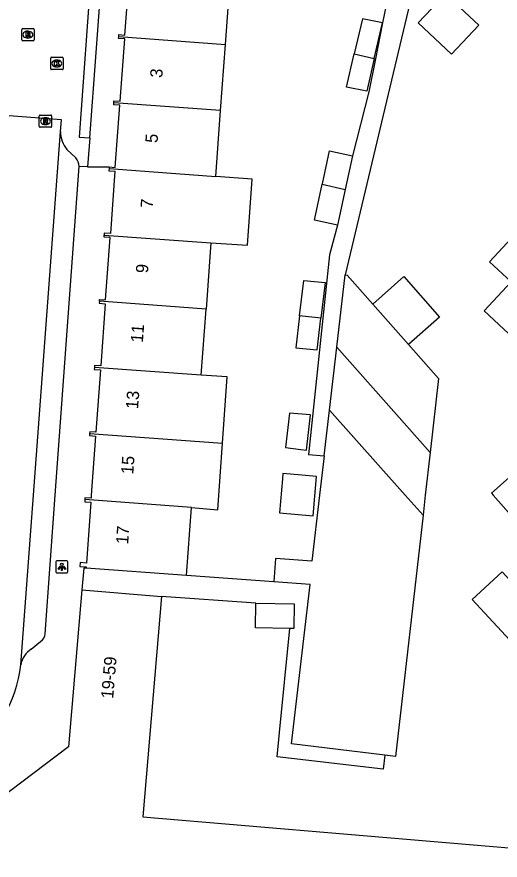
# Model space of a CAD drawing. Extents: x 159961 to 160856, y 382704 to 383353.
# Drawn here: x 160586.5 to 160625.9, y 382970.3 to 383038.9 of the extents above; entities that cross this region are included whole.
import ezdxf

# ---------------------------------------------------------------- set-up
doc = ezdxf.new("R2010")
doc.units = 0
for name, color, linetype in [('IMGEO_Kolk', 7, 'Continuous'), ('IMGEO_Lichtpunt', 7, 'Continuous'), ('IMGEO_Pand', 7, 'Continuous'), ('IMGEO_Pand_nummerreeks', 7, 'Continuous'), ('IMGEO_Rijbaan_lokaal_open', 7, 'Continuous'), ('IMGEO_Rioolput', 7, 'Continuous'), ('IMGEO_Voetpad_open', 7, 'Continuous')]:
    doc.layers.add(name, color=color, linetype=linetype)

msp = doc.modelspace()

# ---------------------------------------------------------------- linework, layer by layer
at = {"layer": 'IMGEO_Kolk'}
for p, q in [((160589.296, 383034.709), (160589.296, 383035.561)), ((160589.371, 383035.635), (160590.223, 383035.635)), ((160589.784, 383035.415), (160589.809, 383035.415)), ((160590.297, 383035.561), (160590.297, 383034.709)), ((160590.223, 383034.635), (160589.371, 383034.635)), ((160589.807, 383034.855), (160589.782, 383034.855))]:
    msp.add_line(p, q, dxfattribs=at)
for points in [[(160589.296, 383034.709), (160589.296, 383035.561)], [(160589.371, 383035.635), (160590.223, 383035.635)], [(160589.617, 383035.335), (160589.74, 383035.335), (160589.74, 383035.184), (160589.87, 383035.335), (160590.034, 383035.335), (160589.888, 383035.184), (160590.041, 383034.935), (160589.889, 383034.935), (160589.804, 383035.099), (160589.74, 383035.032), (160589.74, 383034.935), (160589.617, 383034.935), (160589.617, 383035.335)], [(160590.297, 383035.561), (160590.297, 383034.709)], [(160590.223, 383034.635), (160589.371, 383034.635)]]:
    msp.add_lwpolyline(points, dxfattribs=at)
for centre, start, end in [((160589.373, 383035.559), 91.55205, 178.44795), ((160589.373, 383035.559), 91.55205, 178.44795), ((160590.221, 383035.559), 1.55205, 88.44795), ((160590.221, 383035.559), 1.55205, 88.44795), ((160589.373, 383034.711), 181.55205, 268.44795), ((160589.373, 383034.711), 181.55205, 268.44795), ((160590.221, 383034.711), 271.55205, 358.44795), ((160590.221, 383034.711), 271.55205, 358.44795)]:
    msp.add_arc(centre, 0.0765, start, end, dxfattribs=at)
for centre, major_axis, ratio, start_param, end_param in [((160589.783, 383035.135), (-0.387, 0.002), 0.722429, 4.712389, 7.853982), ((160589.808, 383035.135), (-0.39, 0.002), 0.717154, 1.570796, 4.712389)]:
    msp.add_ellipse(centre, major_axis=major_axis, ratio=ratio, start_param=start_param, end_param=end_param, dxfattribs=at)
at = {"layer": 'IMGEO_Lichtpunt'}
for p, q in [((160589.704, 382994.567), (160589.704, 382993.76)), ((160589.704, 382994.567), (160589.704, 382993.76)), ((160590.606, 382994.662), (160589.798, 382994.662)), ((160590.606, 382994.662), (160589.798, 382994.662)), ((160590.7, 382993.76), (160590.7, 382994.567)), ((160590.7, 382993.76), (160590.7, 382994.567)), ((160589.798, 382993.666), (160590.606, 382993.666)), ((160589.798, 382993.666), (160590.606, 382993.666))]:
    msp.add_line(p, q, dxfattribs=at)
for points in [[(160590.078, 382994.231), (160590.117, 382994.203), (160589.929, 382993.941), (160589.891, 382993.968), (160590.078, 382994.231)], [(160590.18, 382994.183), (160590.227, 382994.183), (160590.227, 382993.861), (160590.18, 382993.861), (160590.18, 382994.183)], [(160590.29, 382994.203), (160590.328, 382994.23), (160590.515, 382993.968), (160590.476, 382993.94), (160590.29, 382994.203)]]:
    msp.add_lwpolyline(points, dxfattribs=at)
msp.add_circle((160590.203, 382994.365), 0.0994, dxfattribs=at)
for centre, start, end in [((160589.798, 382994.567), 90, 180), ((160589.798, 382994.567), 90, 180), ((160590.606, 382994.567), 0, 90), ((160590.606, 382994.567), 0, 90), ((160589.798, 382993.76), 180, 270), ((160589.798, 382993.76), 180, 270), ((160590.606, 382993.76), 270, 0), ((160590.606, 382993.76), 270, 360)]:
    msp.add_arc(centre, 0.0946, start, end, dxfattribs=at)
at = {"layer": 'IMGEO_Pand'}
for points in [[(160594.825, 383037.329), (160594.836, 383037.485), (160595.335, 383037.448), (160595.698, 383042.407), (160595.199, 383042.443), (160595.222, 383042.762)], [(160603.5, 383036.679), (160603.907, 383042.26)], [(160621.894, 383035.902), (160619.197, 383038.43), (160621.41, 383040.791), (160624.107, 383038.263), (160621.894, 383035.902)], [(160616.288, 383038.454), (160614.648, 383038.777), (160613.991, 383035.917)], [(160615.618, 383035.538), (160616.288, 383038.454)], [(160594.431, 383031.938), (160594.442, 383032.098), (160594.941, 383032.061), (160595.313, 383037.13), (160594.813, 383037.166), (160594.825, 383037.329)], [(160594.825, 383037.329), (160603.5, 383036.679)], [(160603.107, 383031.299), (160603.5, 383036.679)], [(160615.618, 383035.538), (160615.005, 383032.871), (160613.365, 383033.194), (160613.991, 383035.917)], [(160613.991, 383035.917), (160615.618, 383035.538)], [(160594.049, 383026.71), (160594.547, 383026.674), (160594.919, 383031.743), (160594.419, 383031.778), (160594.431, 383031.938)], [(160603.107, 383031.299), (160594.431, 383031.938)], [(160602.716, 383025.933), (160603.107, 383031.299)], [(160611.382, 383025.308), (160611.39, 383025.344), (160611.962, 383028.013), (160613.835, 383027.611)], [(160613.835, 383027.611), (160613.25, 383024.883)], [(160594.04, 383026.579), (160594.026, 383026.391), (160594.525, 383026.356), (160594.153, 383021.287), (160593.655, 383021.324), (160593.644, 383021.169)], [(160594.049, 383026.71), (160594.04, 383026.579)], [(160594.04, 383026.579), (160602.716, 383025.933)], [(160602.322, 383020.538), (160605.31, 383020.339), (160605.687, 383025.728), (160602.716, 383025.933)], [(160612.627, 383021.976), (160610.754, 383022.377), (160611.382, 383025.308)], [(160611.382, 383025.308), (160613.25, 383024.883)], [(160613.25, 383024.883), (160612.627, 383021.976)], [(160626.742, 383017.376), (160624.996, 383018.988), (160626.788, 383020.91), (160629.302, 383023.608), (160632.909, 383020.247), (160636.969, 383016.463), (160639.728, 383013.893), (160643.385, 383010.484)], [(160593.252, 383015.798), (160593.262, 383015.937), (160593.76, 383015.9), (160594.131, 383020.969), (160593.632, 383021.005), (160593.644, 383021.169)], [(160593.644, 383021.169), (160602.322, 383020.538)], [(160602.322, 383020.538), (160601.929, 383015.148)], [(160612.571, 383012.052), (160613.257, 383017.926)], [(160613.257, 383017.926), (160613.407, 383017.912), (160615.49, 383015.555)], [(160609.536, 383014.607), (160609.877, 383017.478), (160611.616, 383017.315), (160611.27, 383014.404)], [(160615.49, 383015.555), (160618.011, 383017.784), (160620.93, 383014.482), (160618.409, 383012.254)], [(160629.956, 383014.409), (160627.756, 383012.026), (160624.542, 383014.992), (160626.742, 383017.376)], [(160593.252, 383015.798), (160593.239, 383015.618), (160593.738, 383015.582), (160593.366, 383010.513), (160592.867, 383010.55), (160592.856, 383010.399)], [(160601.929, 383015.148), (160593.252, 383015.798)], [(160615.49, 383015.555), (160618.409, 383012.254)], [(160601.536, 383009.765), (160601.929, 383015.148)], [(160609.536, 383014.607), (160609.225, 383012.001), (160610.965, 383011.838), (160611.27, 383014.404)], [(160611.27, 383014.404), (160609.536, 383014.607)], [(160611.972, 383006.916), (160612.571, 383012.052)], [(160612.571, 383012.052), (160620.162, 383003.469)], [(160618.409, 383012.254), (160620.851, 383009.492), (160620.162, 383003.469)], [(160592.856, 383010.399), (160592.844, 383010.231), (160593.344, 383010.196), (160592.972, 383005.127), (160592.474, 383005.163), (160592.464, 383005.019)], [(160601.536, 383009.765), (160592.856, 383010.399)], [(160603.277, 383004.232), (160603.652, 383009.621), (160601.536, 383009.765)], [(160609.65, 383003.717), (160610.098, 383003.66), (160610.433, 383006.525), (160608.719, 383006.672), (160608.392, 383003.875), (160609.65, 383003.717)], [(160611.539, 383003.213), (160611.972, 383006.916)], [(160619.579, 382998.374), (160618.131, 383000), (160611.972, 383006.916)], [(160592.464, 383005.019), (160592.451, 383004.845), (160592.949, 383004.809), (160592.598, 383000), (160592.58, 382999.752), (160592.083, 382999.789), (160592.072, 382999.639)], [(160592.464, 383005.019), (160603.277, 383004.232)], [(160600.752, 382999.008), (160602.9, 382998.811), (160603.277, 383004.232)], [(160611.539, 383003.213), (160611.164, 383000), (160610.538, 382994.634), (160607.576, 382994.848), (160607.439, 382992.952)], [(160620.162, 383003.469), (160619.765, 383000), (160619.579, 382998.374)], [(160633.574, 382995.462), (160633.496, 382995.551), (160629.562, 383000), (160627.547, 383002.279), (160625.149, 383000.16), (160625.291, 383000), (160630.446, 382994.167), (160633.33, 382993.755), (160632.574, 382988.48)], [(160609.734, 383001.632), (160608.183, 383001.765), (160608.147, 383001.341), (160607.907, 382998.554), (160610.639, 382998.319), (160610.916, 383001.53), (160609.734, 383001.632)], [(160592.072, 382999.639), (160592.06, 382999.47), (160592.558, 382999.434), (160592.196, 382994.476), (160591.699, 382994.514), (160591.676, 382994.195), (160592.175, 382994.16), (160592.168, 382994.051)], [(160600.752, 382999.008), (160592.072, 382999.639)], [(160600.347, 382993.462), (160600.752, 382999.008)], [(160619.579, 382998.374), (160617.333, 382978.743), (160616.467, 382978.846)], [(160600.347, 382993.462), (160592.168, 382994.051)], [(160632.574, 382988.48), (160630.661, 382988.75), (160626.022, 382993.77), (160623.586, 382991.519), (160631.747, 382982.688), (160639.599, 382981.565)], [(160616.467, 382978.846), (160608.885, 382979.749), (160610.401, 382992.738), (160607.439, 382992.952)], [(160591.84, 382992.307), (160590.754, 382979.528), (160583.117, 382973.762)], [(160591.84, 382992.307), (160598.307, 382991.758)], [(160598.307, 382991.758), (160596.782, 382973.814), (160638.396, 382970.297)], [(160608.745, 382989.162), (160605.949, 382989.203), (160605.978, 382991.204)], [(160605.978, 382991.204), (160609.11, 382991.158), (160609.081, 382989.157), (160608.745, 382989.162)]]:
    msp.add_lwpolyline(points, dxfattribs=at)
at = {"layer": 'IMGEO_Rijbaan_lokaal_open'}
for points in [[(160593.395, 383043.012), (160592.619, 383043.056), (160591.618, 383029.136), (160592.486, 383029.073)], [(160590.095, 383029.585), (160590.181, 383030.558), (160585.928, 383030.861)], [(160586.859, 382986.185), (160587.889, 383000), (160590.095, 383029.585)], [(160592.486, 383029.073), (160592.299, 383026.734)], [(160591.342, 383027.461), (160590.616, 383028.128)], [(160592.299, 383026.734), (160591.616, 383026.743)]]:
    msp.add_lwpolyline(points, dxfattribs=at)
for centre, radius, start, end in [((160592.324, 383029.561), 2.23, 179.37225, 219.98023), ((160590.502, 383026.729), 1.114, 0.71505, 41.06022), ((160577.083, 382987.149), 9.823, 302.22896, 354.37083)]:
    msp.add_arc(centre, radius, start, end, dxfattribs=at)
at = {"layer": 'IMGEO_Rioolput'}
for p, q in [((160586.942, 383037.054), (160586.942, 383037.906)), ((160587.017, 383037.98), (160587.869, 383037.98)), ((160587.943, 383037.906), (160587.943, 383037.054)), ((160587.453, 383037.2), (160587.428, 383037.2)), ((160587.43, 383037.76), (160587.455, 383037.76)), ((160587.869, 383036.98), (160587.017, 383036.98)), ((160588.446, 383030.939), (160589.298, 383030.939)), ((160588.371, 383030.013), (160588.371, 383030.865)), ((160588.859, 383030.719), (160588.884, 383030.719)), ((160589.372, 383030.865), (160589.372, 383030.013)), ((160589.298, 383029.939), (160588.446, 383029.939)), ((160588.882, 383030.159), (160588.857, 383030.159))]:
    msp.add_line(p, q, dxfattribs=at)
for points in [[(160586.942, 383037.054), (160586.942, 383037.906)], [(160587.017, 383037.98), (160587.869, 383037.98)], [(160587.943, 383037.906), (160587.943, 383037.054)], [(160587.531, 383037.678), (160587.279, 383037.68), (160587.279, 383037.28)], [(160587.279, 383037.28), (160587.403, 383037.28), (160587.403, 383037.442), (160587.414, 383037.442)], [(160587.457, 383037.599), (160587.403, 383037.599), (160587.403, 383037.518)], [(160587.403, 383037.518), (160587.455, 383037.518)], [(160587.461, 383037.413), (160587.532, 383037.28), (160587.672, 383037.28), (160587.607, 383037.406)], [(160587.869, 383036.98), (160587.017, 383036.98)], [(160588.446, 383030.939), (160589.298, 383030.939)], [(160588.371, 383030.013), (160588.371, 383030.865)], [(160588.96, 383030.637), (160588.708, 383030.639), (160588.708, 383030.239)], [(160588.708, 383030.239), (160588.832, 383030.239), (160588.832, 383030.401), (160588.843, 383030.401)], [(160588.886, 383030.558), (160588.832, 383030.558), (160588.832, 383030.477)], [(160588.832, 383030.477), (160588.884, 383030.477)], [(160588.89, 383030.372), (160588.961, 383030.239), (160589.101, 383030.239), (160589.036, 383030.365)], [(160589.372, 383030.865), (160589.372, 383030.013)], [(160589.298, 383029.939), (160588.446, 383029.939)]]:
    msp.add_lwpolyline(points, dxfattribs=at)
for centre, radius, start, end in [((160587.019, 383037.904), 0.0765, 91.55205, 178.44795), ((160587.019, 383037.904), 0.0765, 91.55205, 178.44795), ((160587.867, 383037.904), 0.0765, 1.55205, 88.44795), ((160587.867, 383037.904), 0.0765, 1.55205, 88.44795), ((160587.413, 383037.389), 0.0533, 26.02933, 88.69889), ((160587.439, 383037.707), 0.19, 274.7715, 282.96867), ((160587.463, 383037.503), 0.0964, 77.00612, 93.18647), ((160587.477, 383037.56), 0.0378, 276.66336, 79.67722), ((160587.53, 383037.568), 0.109, 350.36119, 89.41601), ((160587.528, 383037.568), 0.112, 277.58423, 350.98172), ((160587.512, 383037.353), 0.108, 29.51342, 73.79051), ((160587.019, 383037.056), 0.0765, 181.55205, 268.44795), ((160587.019, 383037.056), 0.0765, 181.55205, 268.44795), ((160587.867, 383037.056), 0.0765, 271.55205, 358.44795), ((160587.867, 383037.056), 0.0765, 271.55205, 358.44795), ((160588.448, 383030.863), 0.0765, 91.55205, 178.44795), ((160588.448, 383030.863), 0.0765, 91.55205, 178.44795), ((160589.296, 383030.863), 0.0765, 1.55205, 88.44795), ((160589.296, 383030.863), 0.0765, 1.55205, 88.44795), ((160588.842, 383030.348), 0.0533, 26.02933, 88.69889), ((160588.868, 383030.666), 0.19, 274.7715, 282.96867), ((160588.892, 383030.462), 0.0964, 77.00612, 93.18647), ((160588.906, 383030.519), 0.0378, 276.66336, 79.67722), ((160588.959, 383030.527), 0.109, 350.36119, 89.41601), ((160588.957, 383030.527), 0.112, 277.58423, 350.98172), ((160588.941, 383030.312), 0.108, 29.51342, 73.79051), ((160588.448, 383030.015), 0.0765, 181.55205, 268.44795), ((160588.448, 383030.015), 0.0765, 181.55205, 268.44795), ((160589.296, 383030.015), 0.0765, 271.55205, 358.44795), ((160589.296, 383030.015), 0.0765, 271.55205, 358.44795)]:
    msp.add_arc(centre, radius, start, end, dxfattribs=at)
for centre, major_axis, ratio, start_param, end_param in [((160587.429, 383037.48), (-0.387, 0.002), 0.722429, 4.712389, 7.853982), ((160587.454, 383037.48), (-0.39, 0.002), 0.717154, 1.570796, 4.712389), ((160588.858, 383030.439), (-0.387, 0.002), 0.722429, 4.712389, 7.853982), ((160588.883, 383030.439), (-0.39, 0.002), 0.717154, 1.570796, 4.712389)]:
    msp.add_ellipse(centre, major_axis=major_axis, ratio=ratio, start_param=start_param, end_param=end_param, dxfattribs=at)
at = {"layer": 'IMGEO_Voetpad_open'}
for points in [[(160619.711, 383045.542), (160618.765, 383041.217), (160613.257, 383017.926)], [(160592.486, 383029.073), (160593.497, 383043.006), (160593.395, 383043.012)], [(160603.907, 383042.26), (160616.876, 383041.35), (160616.288, 383038.454)], [(160616.288, 383038.454), (160615.71, 383035.517), (160615.181, 383032.836), (160613.835, 383027.611)], [(160588.852, 382988.722), (160589.672, 383000), (160591.616, 383026.743)], [(160592.299, 383026.734), (160594.049, 383026.71)], [(160612.627, 383021.976), (160611.969, 383019.573), (160610.253, 383003.323), (160611.539, 383003.213)], [(160592.168, 382994.051), (160591.989, 382994.064), (160591.84, 382992.307)], [(160607.439, 382992.952), (160600.347, 382993.462)], [(160605.978, 382991.204), (160598.307, 382991.758)], [(160616.467, 382978.846), (160616.33, 382977.69), (160607.725, 382978.715), (160607.917, 382980.675), (160608.745, 382989.162)], [(160587.72, 382987.48), (160588.479, 382988.104)]]:
    msp.add_lwpolyline(points, dxfattribs=at)
for centre, radius, start, end in [((160587.934, 382988.854), 0.927, 305.9734, 351.79961), ((160588.832, 382985.807), 2.009, 123.61225, 169.15068)]:
    msp.add_arc(centre, radius, start, end, dxfattribs=at)

# ---------------------------------------------------------------- texts
at = {"layer": 'IMGEO_Pand_nummerreeks'}
for s, rotation, p in [('3', 85.81905, (160598.368, 383033.941)), ('5', 85.81905, (160597.981, 383028.64)), ('7', 85.81905, (160597.593, 383023.34)), ('9', 85.81905, (160597.206, 383018.039)), ('11', 85.81905, (160596.792, 383012.394)), ('13', 85.81905, (160596.397, 383006.979)), ('15', 85.81905, (160596.009, 383001.678)), ('17', 85.82406, (160595.594, 382995.983)), ('19-59', 85.14249, (160594.377, 382983.413))]:
    msp.add_text(s, height=1, rotation=rotation, dxfattribs=at).set_placement(p)

doc.saveas('drawing.dxf')
